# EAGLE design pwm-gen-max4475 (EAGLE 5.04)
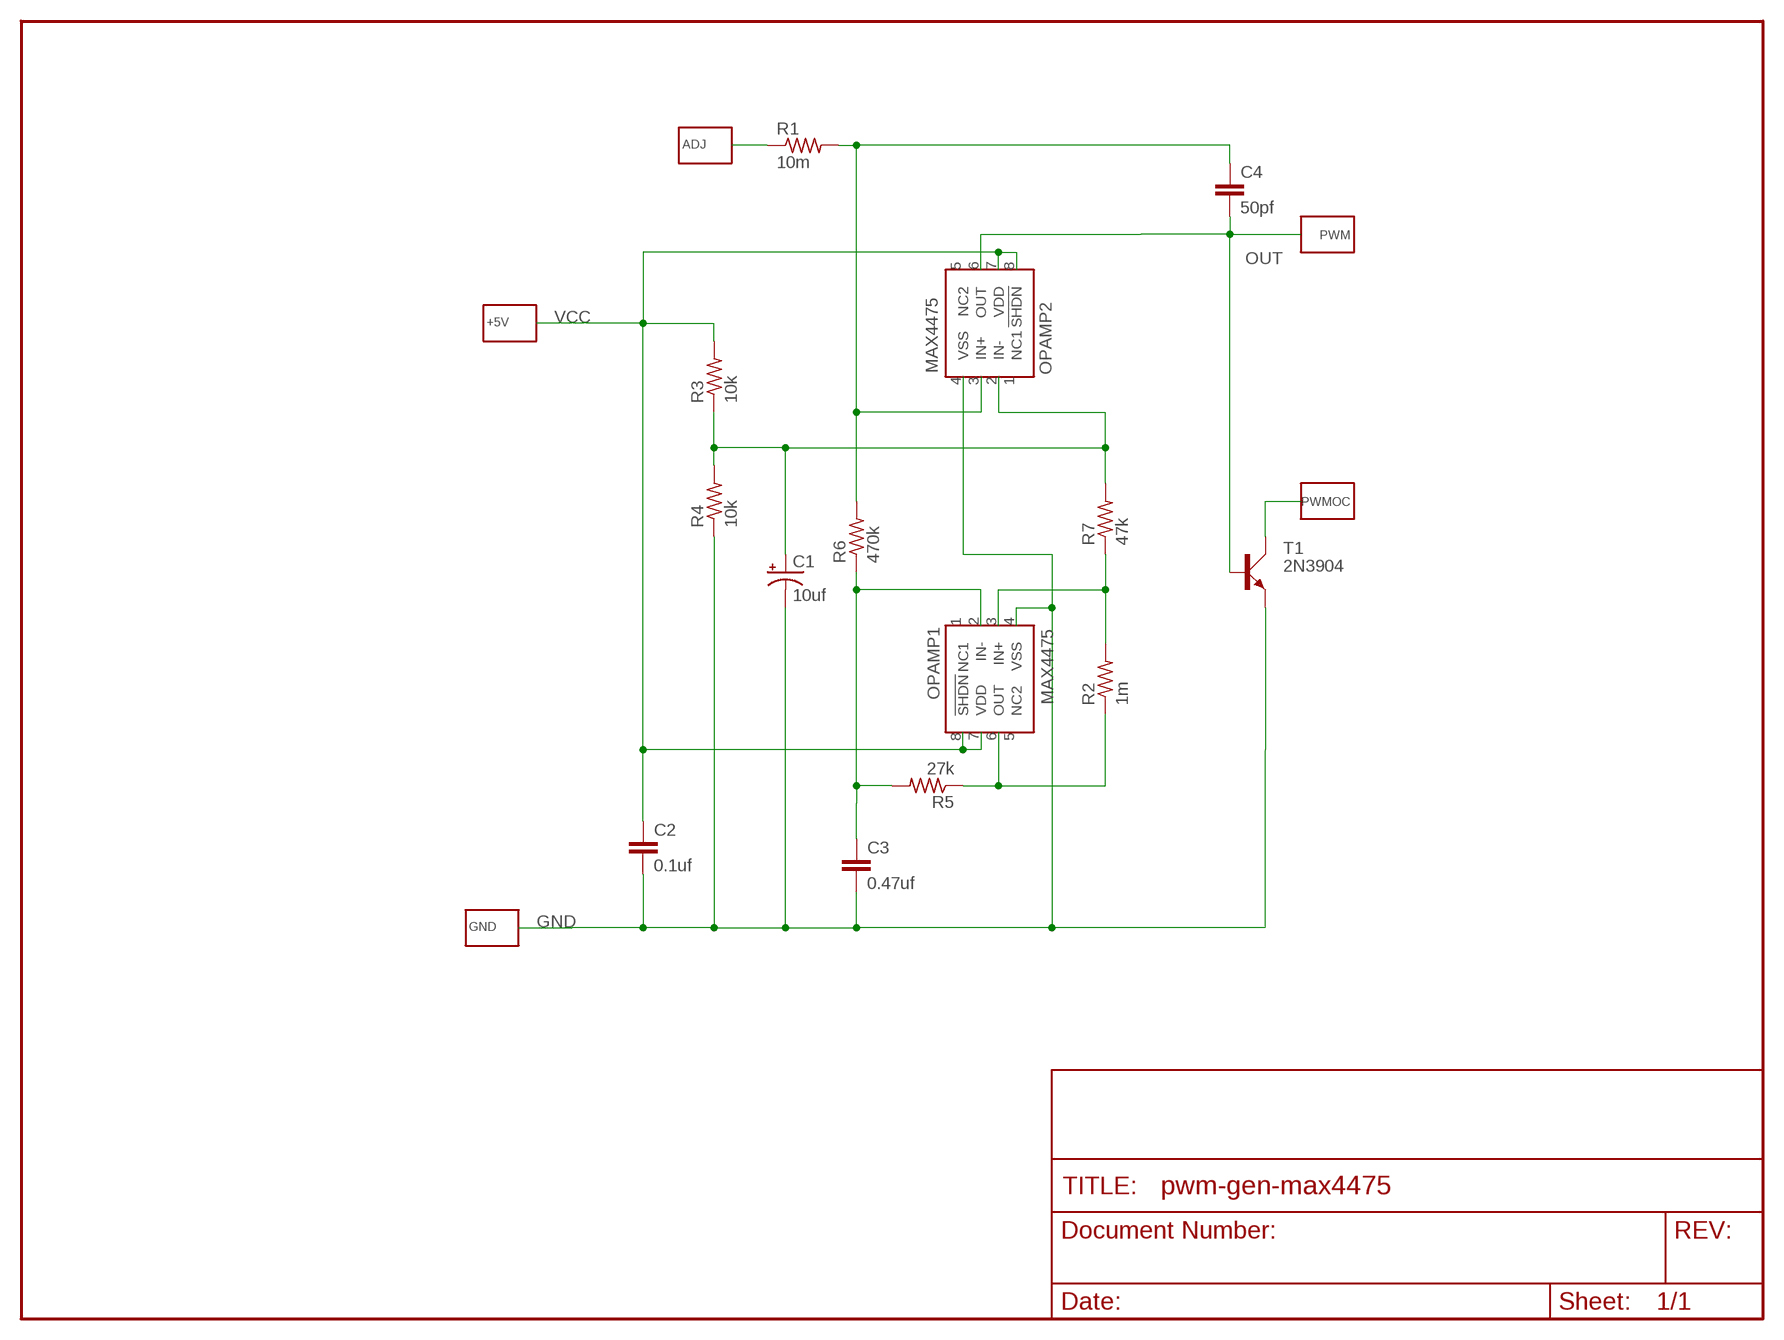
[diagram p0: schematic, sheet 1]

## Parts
+5V  WIREPAD-SMD-NO-VALUE  [WIREPAD-SMD]
ADJ  WIREPAD-SMD-NO-VALUE  [WIREPAD-SMD]
C1  10uf  CPOL-USE2-5  [E2-5]
C2  0.1uf  C-EU050-024X044  [C050-024X044]
C3  0.47uf  C-EU050-024X044  [C050-024X044]
C4  50pf  C-EU050-024X044  [C050-024X044]
GND  WIREPAD-SMD-NO-VALUE  [WIREPAD-SMD]
OPAMP1  MAX4475  [8SOIC]
OPAMP2  MAX4475  [8SOIC]
PWM  WIREPAD-SMD-NO-VALUE  [WIREPAD-SMD]
PWMOC  WIREPAD-SMD-NO-VALUE  [WIREPAD-SMD]
R1  10m  R-US_0207/7  [0207/7]
R2  1m  R-US_0204/7  [0204/7]
R3  10k  R-US_0204/7  [0204/7]
R4  10k  R-US_0204/7  [0204/7]
R5  27k  R-US_0204/7  [0204/7]
R6  470k  R-US_0207/7  [0207/7]
R7  47k  R-US_0207/7  [0207/7]
T1  2N3904  [TO92D]

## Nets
GND: C1.- C2.2 C3.2 GND.1(P) OPAMP1.4(VSS) OPAMP2.4(VSS) R4.1 T1.E
N$1: ADJ.1(P) R1.1
N$2: OPAMP1.6(OUT) R2.1 R5.1
N$3: OPAMP1.3(IN+) R2.2 R7.1
N$4: C1.+ OPAMP2.2(IN-) R3.1 R4.2 R7.2
N$5: C4.1 OPAMP2.3(IN+) R1.2 R6.2
N$7: PWMOC.1(P) T1.C
N$9: C3.1 OPAMP1.2(IN-) R5.2 R6.1
OUT: C4.2 OPAMP2.6(OUT) PWM.1(P) T1.B
VCC: +5V.1(P) C2.1 OPAMP1.7(VDD) OPAMP1.8(!SHDN) OPAMP2.7(VDD) OPAMP2.8(!SHDN) R3.2
Unconnected: OPAMP1.1(NC1) OPAMP1.5(NC2) OPAMP2.1(NC1) OPAMP2.5(NC2)

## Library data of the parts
+5V ADJ GND PWM PWMOC = trl:WIREPAD-SMD-NO-VALUE
C1 = resistor:CPOL-US: POLARIZED CAPACITOR, American symbol
C2-C4 = rcl:C-EU: CAPACITOR, European symbol
OPAMP1 OPAMP2 = trl:MAX4475
R1 R6 R7 = resistor:R-US_: RESISTOR, American symbol
R2-R5 = rcl:R-US_: RESISTOR, American symbol
T1 = transistor-small-signal:2N3904: NPN TRANSISTOR

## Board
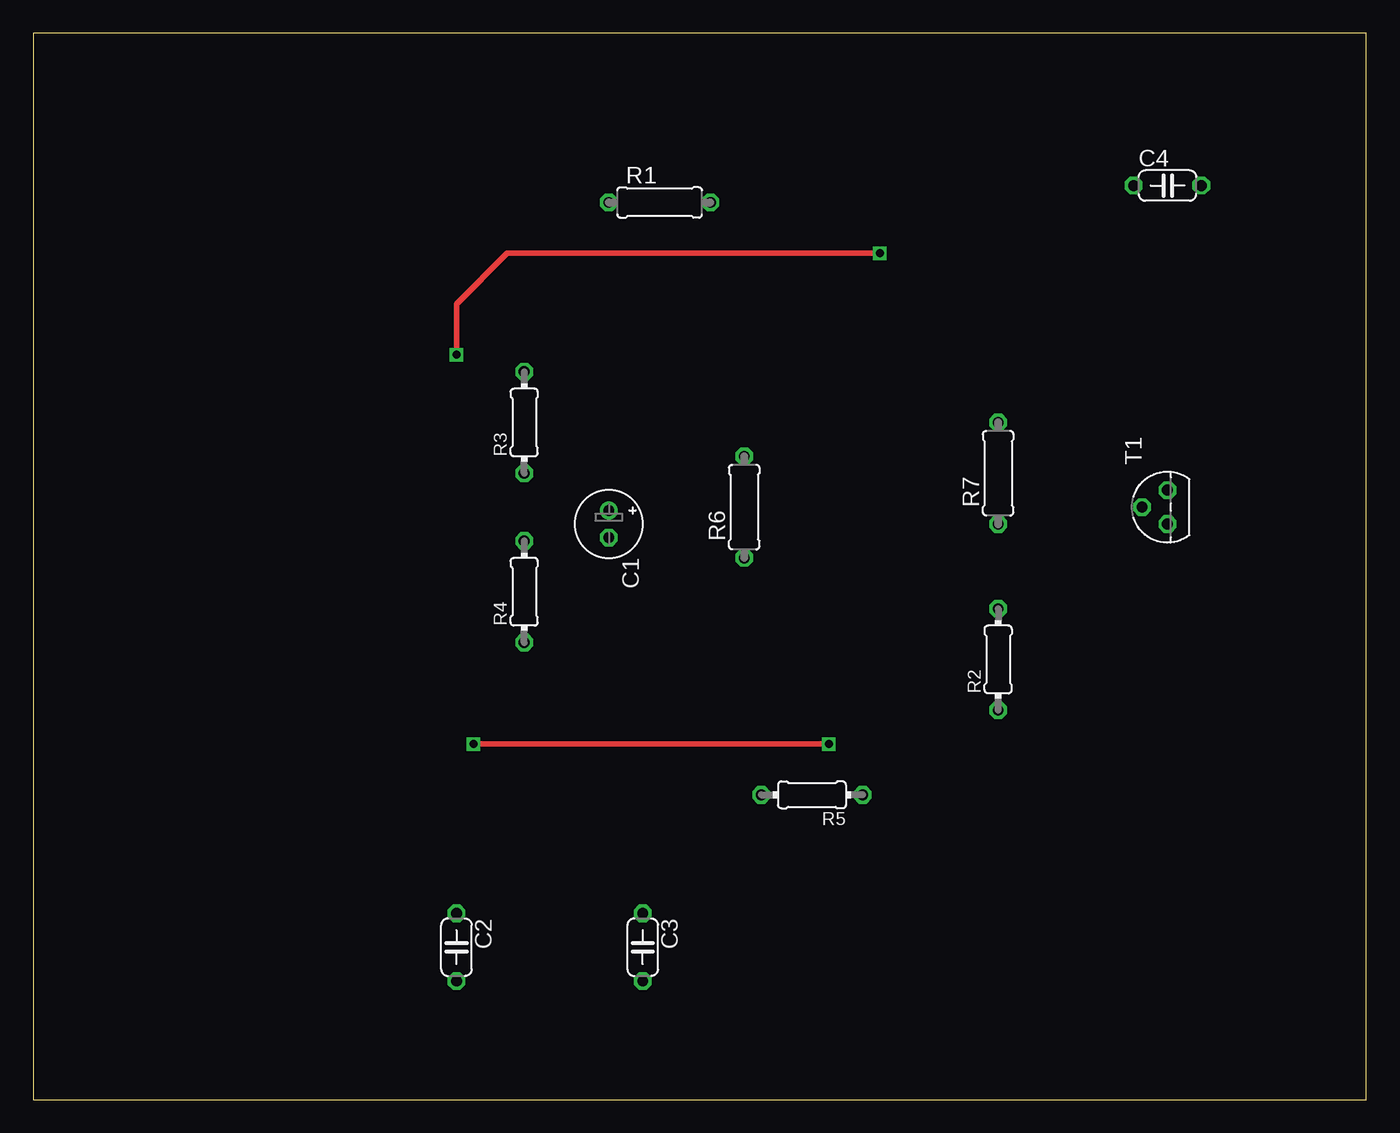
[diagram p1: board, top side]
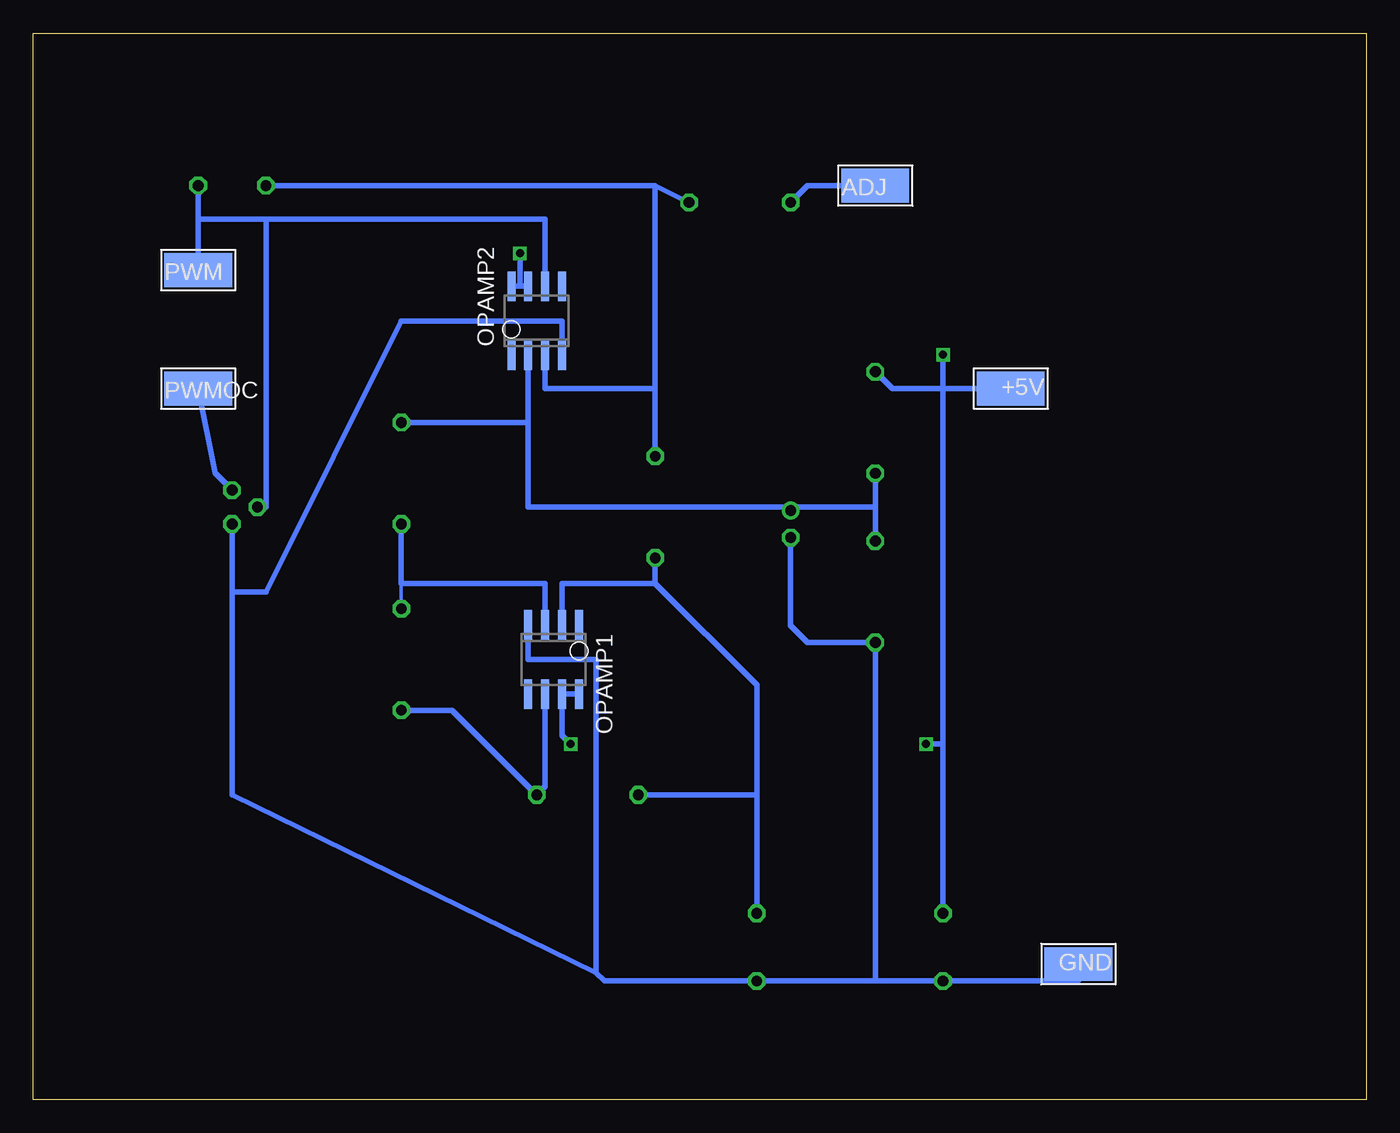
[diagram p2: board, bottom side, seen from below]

Size 100 x 80 mm. Coordinates in mm from the lower left corner, seen from the top.
Outline: 0,0 100,0 100,80 0,80 0,0
Copper layers (1*16): Top 0.035mm / dielectric 1.5mm / Bottom 0.035mm
Design rules "default *": minimum track width 10mil, minimum drill 24mil, track to track 8mil, track to pad 8mil, pad to pad 8mil, via to via 8mil, smd to smd 8mil, copper to edge 40mil, drill to drill 8mil, minimum pad ring 10mil, minimum via ring 8mil, stop-mask expansion 4mil, vias tented up to drill 0mil, thermal gap 10mil

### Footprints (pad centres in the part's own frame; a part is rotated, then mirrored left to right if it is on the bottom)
WIREPAD-SMD = smd 2.54 x 5.08: 1 0,0
E2-5 = drill 0.813 pad 1.27 round: + -1.016,0 | drill 0.813 pad 1.27 octagon: - 1.016,0
C050-024X044 = drill 0.813 octagon: 1 -2.54,0; 2 2.54,0
8SOIC = smd 0.6 x 2.2: 1 -1.905,-2.6; 2 -0.635,-2.6; 3 0.635,-2.6; 4 1.905,-2.6; 5 1.905,2.6; 6 0.635,2.6; 7 -0.635,2.6; 8 -1.905,2.6
0207/7 = drill 0.813 octagon: 1 -3.81,0; 2 3.81,0
0204/7 = drill 0.813 octagon: 1 -3.81,0; 2 3.81,0
TO92D = drill 0.813 octagon: B 0,1.905; C 1.27,0; E -1.27,0

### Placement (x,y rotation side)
+5V  26.67,53.34 90 bottom
ADJ  36.83,68.58 270 bottom
C1  43.18,43.18 270 top
C2  31.75,11.43 270 top
C3  45.72,11.43 270 top
C4  85.09,68.58 0 top
GND  21.59,10.16 90 bottom
OPAMP1  60.96,33.02 180 bottom
OPAMP2  62.23,58.42 0 bottom
PWM  87.63,62.23 270 bottom
PWMOC  87.63,53.34 270 bottom
R1  46.99,67.31 0 top
R2  72.39,33.02 90 top
R3  36.83,50.8 90 top
R4  36.83,38.1 90 top
R5  58.42,22.86 180 top
R6  53.34,44.45 90 top
R7  72.39,46.99 90 top
T1  85.09,44.45 90 top

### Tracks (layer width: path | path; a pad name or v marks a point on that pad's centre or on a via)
GND
  Bottom 0.406: 36.83,8.89 R4.1 41.91,34.29 43.18,35.56 C1.- | 36.83,8.89 C3.2 57.15,8.89 57.78,9.53 | 36.83,8.89 C2.2 21.59,8.89 GND.1 | 85.09,38.1 85.09,22.86 57.78,9.53 | 85.09,38.1 T1.E | OPAMP1.4 62.87,33.02 57.78,33.02 57.78,20.95 57.78,9.53 | OPAMP2.4 60.33,58.42 66.04,58.42 72.39,58.42 82.55,38.1 85.09,38.1
N$1
  Bottom 0.254: ADJ.1 38.1,68.58
  Bottom 0.406: R1.1 41.91,68.58 38.1,68.58
N$2
  Bottom 0.406: OPAMP1.6 61.59,23.5 R5.1 68.58,29.21 R2.1
N$3
  Bottom 0.254: 72.39,38.73 R2.2
  Bottom 0.406: R7.1 72.39,38.73 61.59,38.73 OPAMP1.3
N$4
  Bottom 0.254: 62.87,44.45 62.87,50.8 | 43.18,44.45 C1.+ 43.18,44.45
  Bottom 0.406: 36.83,44.45 R3.1 | R4.2 36.83,44.45 | 36.83,44.45 43.18,44.45 62.87,44.45 62.87,50.8 | 62.87,50.8 R7.2 | OPAMP2.2 62.87,52.65 62.87,50.8
N$5
  Bottom 0.406: R6.2 53.34,53.34 | 53.34,53.34 53.34,68.58 | 53.34,68.58 R1.2 | 53.34,68.58 C4.1 | OPAMP2.3 61.59,53.34 53.34,53.34
N$7
  Bottom 0.406: T1.C 86.36,46.99 PWMOC.1
N$9
  Bottom 0.406: 53.34,38.73 R6.1 | R5.2 53.34,22.86 45.72,22.86 | OPAMP1.2 60.33,38.73 53.34,38.73 | C3.1 45.72,22.86 | 45.72,22.86 45.72,31.11 53.34,38.73
OUT
  Bottom 0.406: 82.55,66.04 82.55,44.45 T1.B | 87.63,66.04 PWM.1 | 87.63,66.04 C4.2 | 82.55,66.04 61.59,66.04 OPAMP2.6 | 82.55,66.04 87.63,66.04
VCC  (via drill 0.6)
  Top 0.406: v33.02,26.67 v59.69,26.67 | v31.75,55.88 31.75,59.69 35.56,63.5 v63.5,63.5
  Bottom 0.254: 27.94,53.34 +5V.1
  Bottom 0.406: C2.1 31.75,26.67 | 31.75,26.67 31.75,53.34 | 31.75,53.34 27.94,53.34 | R3.2 35.56,53.34 31.75,53.34 | 63.5,61.02 OPAMP2.7 | 63.5,61.02 OPAMP2.8 | OPAMP1.8 OPAMP1.7 60.33,27.3 v59.69,26.67 | 31.75,26.67 v33.02,26.67 | 31.75,53.34 v31.75,55.88 | v63.5,63.5 63.5,61.02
